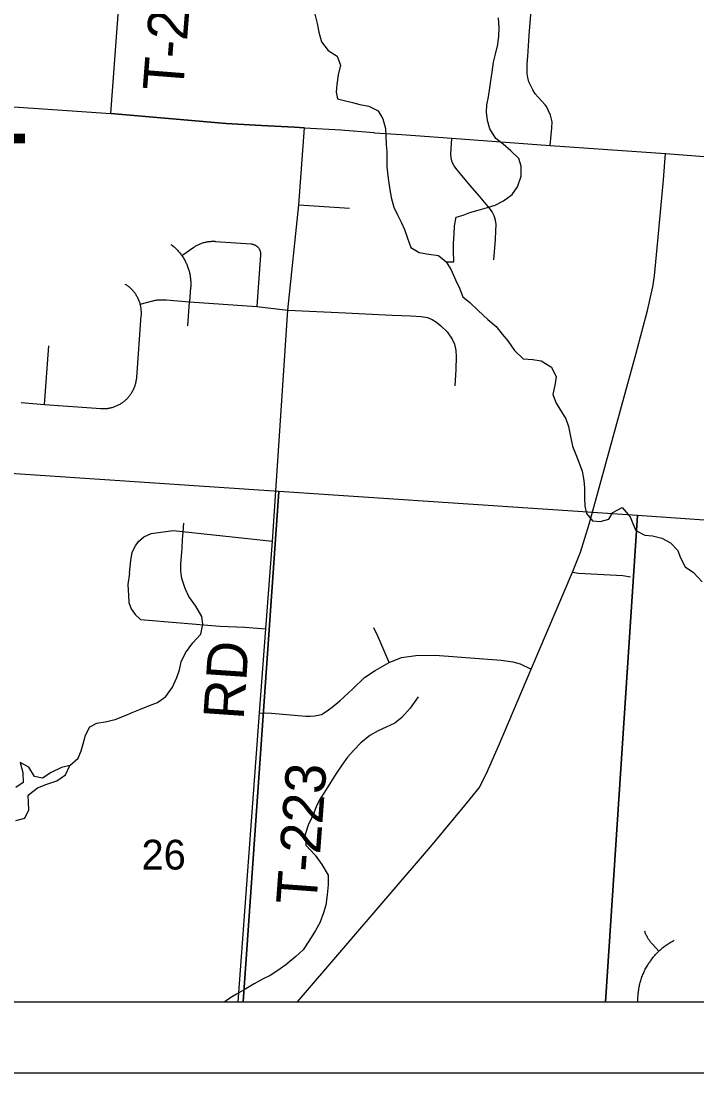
# Model space of a CAD drawing. Extents: x 0 to 34, y 0 to 22.
# Drawn here: x 3.147 to 4.098, y 14 to 15.479 of the extents above; entities that cross this region are included whole.
import ezdxf

# ---------------------------------------------------------------- set-up
doc = ezdxf.new("R2010")
doc.units = 0
for name, color, linetype in [('GM_X_Corporation', 7, 'Continuous'), ('GM_X_County_Road', 7, 'Continuous'), ('GM_X_Minor_Lake', 7, 'Continuous'), ('GM_X_Minor_River', 7, 'Continuous'), ('GM_X_Section_Text', 7, 'Continuous'), ('GM_X_State_Route', 7, 'Continuous'), ('GM_X_State_Shield', 7, 'Continuous'), ('GM_X_Township_Road', 7, 'Continuous'), ('GM_X_Township_Road_Text', 7, 'Continuous'), ('GM_X_Unincorporated_Text', 7, 'Continuous'), ('SH_Cut_Line', 7, 'Continuous'), ('SH_Data', 7, 'Continuous')]:
    doc.layers.add(name, color=color, linetype=linetype)

msp = doc.modelspace()

# ---------------------------------------------------------------- linework, layer by layer
at = {"layer": 'GM_X_Corporation'}
msp.add_lwpolyline([(2.1, 15.9442), (2.1, 14.1), (4.9875, 14.1), (5.0611, 15.2147), (5.0952, 15.7318), (4.92, 15.7429), (4.5905, 15.7634), (4.2803, 15.787), (3.9945, 15.8088), (3.3132, 15.8609), (2.8362, 15.8952), (2.7799, 15.8989), (2.6921, 15.9056), (2.5827, 15.9132), (2.2903, 15.9292)], close=True, dxfattribs=at)
at = {"layer": 'GM_X_County_Road'}
msp.add_lwpolyline([(3.5364, 14.1), (3.7263, 14.3211), (3.7718, 14.3759), (3.7918, 14.401), (3.8015, 14.4199), (3.8205, 14.4627), (3.8648, 14.5679), (3.9228, 14.7043), (3.9343, 14.7323), (3.9465, 14.7715), (4.0126, 15.012), (4.0283, 15.072), (4.0359, 15.1052), (4.0381, 15.1205), (4.0431, 15.1699), (4.051, 15.2555), (4.0539, 15.2928)], dxfattribs=at)
at = {"layer": 'GM_X_Minor_Lake'}
msp.add_lwpolyline([(3.1402, 14.3551), (3.1528, 14.3584), (3.1586, 14.3701), (3.1577, 14.3906), (3.1706, 14.4008), (3.1836, 14.4059), (3.1977, 14.4107), (3.2099, 14.4193), (3.2161, 14.4322), (3.2043, 14.4296), (3.1898, 14.4222), (3.1776, 14.4143), (3.1663, 14.4167), (3.1585, 14.4297), (3.1464, 14.4363), (3.15, 14.4226), (3.1506, 14.4082), (3.1403, 14.4015)], dxfattribs=at)
at = {"layer": 'GM_X_Minor_River'}
for points in [[(3.5608, 15.4888), (3.5641, 15.4755), (3.5662, 15.4633), (3.5702, 15.4496), (3.5796, 15.4373), (3.592, 15.4296), (3.5968, 15.4167), (3.5936, 15.4034), (3.5916, 15.3898), (3.5907, 15.3791), (3.5925, 15.3696), (3.6038, 15.3668), (3.6136, 15.3645), (3.6238, 15.3617), (3.6367, 15.3593), (3.6495, 15.3527), (3.6562, 15.3416), (3.6598, 15.3279), (3.6605, 15.3177), (3.6611, 15.3048), (3.6618, 15.2953), (3.6617, 15.2846), (3.6619, 15.274), (3.6633, 15.2611), (3.6647, 15.2508), (3.6665, 15.239), (3.6686, 15.2291), (3.6715, 15.2173), (3.6771, 15.2066), (3.6827, 15.1952), (3.6867, 15.1857), (3.6908, 15.1735), (3.6955, 15.1605), (3.7072, 15.1536), (3.7208, 15.1511), (3.7344, 15.1491), (3.7453, 15.1403), (3.7524, 15.1292), (3.7583, 15.1151), (3.7639, 15.1032), (3.7687, 15.0914), (3.7784, 15.083), (3.7904, 15.0722), (3.8039, 15.0592), (3.8156, 15.0496), (3.8242, 15.0389), (3.832, 15.0293), (3.8413, 15.0159), (3.8537, 15.004), (3.867, 15.0031), (3.8791, 15.0011), (3.8934, 14.9922), (3.9, 14.9788), (3.8988, 14.9694), (3.8952, 14.9538), (3.9, 14.9416), (3.9075, 14.9294), (3.9134, 14.9195), (3.9175, 14.9088), (3.9203, 14.8947), (3.9228, 14.8814), (3.9276, 14.8696), (3.9321, 14.8589), (3.9365, 14.846), (3.939, 14.8331), (3.94, 14.8228), (3.9399, 14.8088), (3.9405, 14.797), (3.9427, 14.7867), (3.9513, 14.7764)], [(3.7453, 15.1403), (3.7563, 15.1402), (3.7557, 15.1561), (3.7558, 15.1667), (3.7564, 15.1793), (3.7572, 15.191), (3.7593, 15.2031), (3.7691, 15.2061), (3.7787, 15.2098), (3.7904, 15.2131), (3.8034, 15.2167), (3.814, 15.22), (3.8258, 15.226), (3.838, 15.235), (3.8457, 15.2459), (3.8508, 15.261), (3.8506, 15.2751), (3.8473, 15.2857), (3.8364, 15.2965), (3.8255, 15.3057), (3.815, 15.3138), (3.8068, 15.3275), (3.8035, 15.3393), (3.8021, 15.3507), (3.8026, 15.361), (3.8047, 15.3724), (3.8067, 15.3849), (3.8083, 15.3951), (3.81, 15.4072), (3.812, 15.4209), (3.8148, 15.4326), (3.8179, 15.4459), (3.8192, 15.4576), (3.8197, 15.4694), (3.8187, 15.4834)], [(3.9513, 14.7764), (3.9619, 14.7751), (3.974, 14.7784), (3.9798, 14.7882), (3.9928, 14.7949), (4.004, 14.7819), (4.0077, 14.7724), (4.0121, 14.7625), (4.0245, 14.7563), (4.0355, 14.755), (4.0487, 14.7518), (4.0608, 14.7453), (4.0709, 14.7345), (4.0742, 14.725), (4.0816, 14.7116), (4.0933, 14.7035), (4.1053, 14.6905)], [(3.2161, 14.4322), (3.2279, 14.4427), (3.2322, 14.4529), (3.235, 14.4627), (3.2381, 14.4748), (3.2443, 14.4865), (3.2542, 14.4917), (3.266, 14.4939), (3.28, 14.4968), (3.293, 14.502), (3.3036, 14.5068), (3.3154, 14.5116), (3.328, 14.5168), (3.3394, 14.5208), (3.3512, 14.5291), (3.3604, 14.5426), (3.3666, 14.5559), (3.3702, 14.5668), (3.3729, 14.5782), (3.3788, 14.5906), (3.3891, 14.6046), (3.4003, 14.617), (3.4031, 14.631), (3.4017, 14.6416), (3.3931, 14.6562), (3.3834, 14.6699), (3.3782, 14.681), (3.3735, 14.6951), (3.3721, 14.7057), (3.3722, 14.7156), (3.373, 14.7266), (3.3739, 14.7376), (3.3744, 14.7501), (3.3753, 14.7603), (3.3766, 14.7732)], [(3.7058, 14.5288), (3.6946, 14.513), (3.6831, 14.4998), (3.6732, 14.4919), (3.661, 14.486), (3.6499, 14.4808), (3.6381, 14.4745), (3.6255, 14.464), (3.6156, 14.4538), (3.6067, 14.444), (3.5987, 14.4327), (3.5914, 14.4222), (3.5825, 14.4082), (3.574, 14.395), (3.5682, 14.3852), (3.5628, 14.3754), (3.5577, 14.3614), (3.5519, 14.3497), (3.5469, 14.3354), (3.5482, 14.3202), (3.5609, 14.306), (3.5706, 14.293), (3.5796, 14.2781), (3.5794, 14.2644), (3.5781, 14.2504), (3.5761, 14.236), (3.5726, 14.225), (3.5675, 14.211), (3.5617, 14.2001), (3.5532, 14.1865), (3.544, 14.1733), (3.534, 14.1636), (3.5199, 14.1519), (3.5073, 14.1433), (3.4977, 14.137), (3.4879, 14.1325), (3.4753, 14.1255), (3.4638, 14.1184), (3.4505, 14.1109), (3.441, 14.1053), (3.4342, 14.1)]]:
    msp.add_lwpolyline(points, dxfattribs=at)
at = {"layer": 'GM_X_State_Route'}
msp.add_line((3.6444, 15.322), (3.6823, 15.3192), dxfattribs=at)
for points in [[(2.7232, 15.3874), (2.7363, 15.3866), (2.7736, 15.3839), (2.8199, 15.3805), (2.911, 15.3744), (2.9933, 15.3683), (3.2738, 15.3489)], [(3.2738, 15.3489), (3.436, 15.3351), (3.4855, 15.332), (3.5321, 15.3297), (3.5463, 15.3288)], [(3.5463, 15.3288), (3.5971, 15.3258), (3.6434, 15.3221), (3.6444, 15.322)], [(3.6823, 15.3192), (3.7023, 15.3178), (3.7533, 15.3145), (3.8914, 15.3041), (4.0539, 15.2928)], [(4.0539, 15.2928), (4.1445, 15.2855), (4.1735, 15.283)]]:
    msp.add_lwpolyline(points, dxfattribs=at)
at = {"layer": 'GM_X_Township_Road'}
for p, q in [((3.5382, 15.2207), (3.6095, 15.2157)), ((3.382, 15.0503), (3.3845, 15.0843)), ((3.1806, 14.94), (3.1866, 15.0222))]:
    msp.add_line(p, q, dxfattribs=at)
for points in [[(3.2738, 15.3489), (3.2886, 15.5518), (3.2988, 15.6689), (3.3006, 15.7403), (3.3081, 15.7684), (3.3134, 15.8604)], [(3.8845, 15.3609), (3.8794, 15.3667), (3.8747, 15.372), (3.8707, 15.3768), (3.8672, 15.3821), (3.8642, 15.3877), (3.8618, 15.3936), (3.86, 15.3996), (3.8591, 15.4052), (3.859, 15.4105), (3.8593, 15.4186), (3.86, 15.4291), (3.8622, 15.4589), (3.866, 15.5055), (3.871, 15.57)], [(3.8914, 15.3041), (3.894, 15.329), (3.8942, 15.337), (3.8921, 15.3468), (3.8864, 15.3587), (3.8845, 15.3609)], [(3.5463, 15.3288), (3.5321, 15.3297), (3.4855, 15.332), (3.436, 15.3351), (3.2738, 15.3489)], [(3.4528, 14.1), (3.4828, 14.5062), (3.4919, 14.6245), (3.5011, 14.7476), (3.5227, 15.0726), (3.5382, 15.2207), (3.5463, 15.3288)], [(3.8125, 15.1432), (3.8145, 15.172), (3.8153, 15.184), (3.8155, 15.1929), (3.8147, 15.1991), (3.8128, 15.2052), (3.8114, 15.2081), (3.8099, 15.2109), (3.8062, 15.216), (3.7922, 15.2326), (3.782, 15.2443), (3.7601, 15.2704), (3.7565, 15.2753), (3.7538, 15.2807), (3.7524, 15.2865), (3.752, 15.2926), (3.7522, 15.2987), (3.7533, 15.3145)], [(3.3582, 15.165), (3.3593, 15.1641), (3.3604, 15.1633), (3.3615, 15.1624), (3.3626, 15.1615), (3.3636, 15.1606), (3.3646, 15.1596), (3.3656, 15.1586), (3.3666, 15.1577), (3.3676, 15.1566), (3.3685, 15.1556), (3.3694, 15.1546), (3.3703, 15.1535), (3.3712, 15.1524), (3.3721, 15.1513), (3.3729, 15.1502), (3.3737, 15.1491), (3.3745, 15.1479), (3.3753, 15.1467), (3.376, 15.1455), (3.3768, 15.1443), (3.3775, 15.143), (3.3782, 15.1418), (3.3788, 15.1405), (3.3794, 15.1392), (3.38, 15.1379), (3.3806, 15.1366), (3.3812, 15.1353), (3.3817, 15.1339), (3.3822, 15.1326), (3.3826, 15.1312), (3.3831, 15.1299), (3.3835, 15.1285), (3.3839, 15.1271), (3.3842, 15.1257), (3.3845, 15.1243), (3.3848, 15.1229), (3.3851, 15.1215), (3.3853, 15.1201), (3.3855, 15.1187), (3.3857, 15.1173), (3.3859, 15.1158), (3.386, 15.1144), (3.3861, 15.113), (3.3861, 15.1116), (3.3862, 15.1101), (3.3862, 15.1087), (3.3861, 15.1073), (3.3861, 15.1058), (3.386, 15.1044), (3.3845, 15.0843)], [(3.3737, 15.1491), (3.3905, 15.1608), (3.3915, 15.1615), (3.3924, 15.1621), (3.3934, 15.1627), (3.3944, 15.1633), (3.3954, 15.1638), (3.3965, 15.1644), (3.3975, 15.1649), (3.3986, 15.1654), (3.3996, 15.1658), (3.4007, 15.1662), (3.4018, 15.1666), (3.4029, 15.167), (3.404, 15.1674), (3.4051, 15.1677), (3.4062, 15.168), (3.4073, 15.1682), (3.4085, 15.1685), (3.4096, 15.1687), (3.4107, 15.1689), (3.4119, 15.169), (3.413, 15.1691), (3.4142, 15.1692), (3.4153, 15.1693), (3.4165, 15.1694), (3.4176, 15.1694), (3.4188, 15.1694), (3.42, 15.1693), (3.4211, 15.1692), (3.4711, 15.1656), (3.4718, 15.1655), (3.4724, 15.1654), (3.473, 15.1653), (3.4736, 15.1651), (3.4743, 15.165), (3.4749, 15.1648), (3.4755, 15.1645), (3.476, 15.1643), (3.4766, 15.164), (3.4772, 15.1637), (3.4777, 15.1634), (3.4782, 15.163), (3.4788, 15.1626), (3.4793, 15.1622), (3.4797, 15.1618), (3.4802, 15.1614), (3.4806, 15.1609), (3.481, 15.1604), (3.4814, 15.1599), (3.4818, 15.1594), (3.4822, 15.1589), (3.4825, 15.1583), (3.4828, 15.1578), (3.4831, 15.1572), (3.4833, 15.1566), (3.4835, 15.156), (3.4837, 15.1554), (3.4839, 15.1548), (3.484, 15.1541), (3.4841, 15.1535), (3.4842, 15.1529), (3.4843, 15.1523), (3.4843, 15.1516), (3.4843, 15.151), (3.4843, 15.1503), (3.4789, 15.0774)], [(3.1475, 14.9424), (3.1806, 14.94), (3.2595, 14.9342), (3.2607, 14.9341), (3.2618, 14.9341), (3.263, 14.934), (3.2642, 14.9341), (3.2654, 14.9341), (3.2666, 14.9342), (3.2677, 14.9343), (3.2689, 14.9344), (3.2701, 14.9346), (3.2712, 14.9348), (3.2724, 14.935), (3.2736, 14.9352), (3.2747, 14.9355), (3.2758, 14.9358), (3.277, 14.9362), (3.2781, 14.9365), (3.2792, 14.9369), (3.2803, 14.9373), (3.2814, 14.9378), (3.2825, 14.9383), (3.2836, 14.9388), (3.2846, 14.9393), (3.2857, 14.9398), (3.2867, 14.9404), (3.2877, 14.941), (3.2887, 14.9417), (3.2897, 14.9423), (3.2907, 14.943), (3.2916, 14.9437), (3.2925, 14.9444), (3.2934, 14.9452), (3.2943, 14.9459), (3.2952, 14.9467), (3.2961, 14.9475), (3.2969, 14.9484), (3.2977, 14.9492), (3.2985, 14.9501), (3.2993, 14.951), (3.3, 14.9519), (3.3007, 14.9529), (3.3014, 14.9538), (3.3021, 14.9548), (3.3028, 14.9558), (3.3034, 14.9568), (3.304, 14.9578), (3.3046, 14.9588), (3.3051, 14.9598), (3.3057, 14.9609), (3.3061, 14.962), (3.3066, 14.9631), (3.3071, 14.9642), (3.3075, 14.9653), (3.3079, 14.9664), (3.3082, 14.9675), (3.3086, 14.9686), (3.3089, 14.9698), (3.3091, 14.9709), (3.3094, 14.9721), (3.3096, 14.9732), (3.3098, 14.9744), (3.31, 14.9756), (3.3101, 14.9767), (3.3102, 14.9779), (3.3166, 15.0649), (3.3167, 15.066), (3.3167, 15.0672), (3.3167, 15.0683), (3.3167, 15.0695), (3.3167, 15.0706), (3.3166, 15.0717), (3.3165, 15.0729), (3.3164, 15.074), (3.3162, 15.0751), (3.3161, 15.0763), (3.3159, 15.0774), (3.3156, 15.0785), (3.3154, 15.0796), (3.3151, 15.0807), (3.3148, 15.0819), (3.3144, 15.083), (3.314, 15.0842), (3.3136, 15.0853), (3.3132, 15.0864), (3.3127, 15.0875), (3.3122, 15.0886), (3.3117, 15.0896), (3.3111, 15.0907), (3.3105, 15.0918), (3.3099, 15.0928), (3.3093, 15.0938), (3.3087, 15.0948), (3.308, 15.0958), (3.3073, 15.0968), (3.3065, 15.0977), (3.3058, 15.0986), (3.305, 15.0995), (3.3042, 15.1004), (3.3034, 15.1013), (3.3026, 15.1021), (3.3017, 15.103), (3.3008, 15.1038), (3.2999, 15.1046), (3.299, 15.1053), (3.298, 15.1061), (3.2971, 15.1068), (3.2961, 15.1075), (3.2951, 15.1081), (3.2941, 15.1087)], [(3.3151, 15.0807), (3.3326, 15.0855), (3.3337, 15.0858), (3.3349, 15.086), (3.336, 15.0863), (3.3371, 15.0865), (3.3382, 15.0866), (3.3394, 15.0868), (3.3405, 15.0869), (3.3416, 15.087), (3.3428, 15.0871), (3.3439, 15.0871), (3.3451, 15.0871), (3.3462, 15.0871), (3.3473, 15.0871), (3.3485, 15.087), (3.3514, 15.0868), (3.3845, 15.0843), (3.4789, 15.0774), (3.5227, 15.0726)], [(3.5227, 15.0726), (3.6037, 15.0687), (3.6694, 15.0655), (3.6955, 15.0643), (3.71, 15.0635), (3.7193, 15.062), (3.7258, 15.0594), (3.7315, 15.0554), (3.7379, 15.0503), (3.7469, 15.0419), (3.7536, 15.0319), (3.7569, 15.0247), (3.7591, 15.0158), (3.7592, 15.0071), (3.7587, 14.9892), (3.7575, 14.966)], [(3.3002, 14.7028), (3.3017, 14.7207), (3.3037, 14.732), (3.3086, 14.7411), (3.3128, 14.7472), (3.3201, 14.7536), (3.3304, 14.7585), (3.3616, 14.7625), (3.5011, 14.7476)], [(3.3002, 14.7028), (3.2978, 14.6869), (3.2985, 14.6714), (3.2992, 14.6615), (3.3023, 14.6524), (3.3079, 14.6444), (3.3155, 14.6375), (3.4271, 14.628), (3.4621, 14.6267), (3.4919, 14.6245)], [(3.9228, 14.7043), (3.9314, 14.7025), (3.9938, 14.6992), (4.0045, 14.6974)], [(3.6651, 14.5772), (3.6499, 14.6134), (3.6437, 14.6259)], [(3.4828, 14.5062), (3.4999, 14.5057), (3.5478, 14.5014), (3.5541, 14.5014), (3.5606, 14.5019), (3.57, 14.5042), (3.5764, 14.5081), (3.585, 14.5143), (3.5957, 14.5233), (3.614, 14.5399), (3.6306, 14.5558), (3.6454, 14.5658), (3.6651, 14.5772), (3.6824, 14.5841), (3.7028, 14.5868), (3.73, 14.5872), (3.8226, 14.5806), (3.8391, 14.5779), (3.8495, 14.5754), (3.8648, 14.5679)], [(4.0446, 14.1713), (4.0353, 14.1812), (4.0345, 14.1821), (4.0337, 14.183), (4.0329, 14.1839), (4.0322, 14.1848), (4.0315, 14.1857), (4.0308, 14.1867), (4.0302, 14.1876), (4.0296, 14.1886), (4.0289, 14.1896), (4.0284, 14.1906), (4.0278, 14.1917), (4.0273, 14.1927), (4.0268, 14.1937), (4.0263, 14.1948), (4.0258, 14.1959), (4.0254, 14.197), (4.025, 14.1981), (4.0246, 14.1992)], [(4.015, 14.1), (4.015, 14.1002), (4.0149, 14.1019), (4.0149, 14.1036), (4.015, 14.1053), (4.015, 14.107), (4.0151, 14.1087), (4.0153, 14.1104), (4.0154, 14.112), (4.0156, 14.1137), (4.0158, 14.1154), (4.0161, 14.1171), (4.0163, 14.1187), (4.0166, 14.1204), (4.017, 14.122), (4.0173, 14.1237), (4.0177, 14.1253), (4.0181, 14.127), (4.0186, 14.1286), (4.0191, 14.1302), (4.0196, 14.1318), (4.0201, 14.1334), (4.0207, 14.135), (4.0213, 14.1366), (4.0219, 14.1382), (4.0226, 14.1397), (4.0232, 14.1413), (4.0239, 14.1428), (4.0247, 14.1443), (4.0254, 14.1458), (4.0262, 14.1473), (4.027, 14.1488), (4.0279, 14.1503), (4.0287, 14.1517), (4.0296, 14.1531), (4.0305, 14.1546), (4.0315, 14.156), (4.0324, 14.1574), (4.0334, 14.1587), (4.0345, 14.1601), (4.0355, 14.1614), (4.0366, 14.1627), (4.0376, 14.164), (4.0387, 14.1653), (4.0399, 14.1665), (4.041, 14.1678), (4.0422, 14.169), (4.0434, 14.1702), (4.0446, 14.1713), (4.0458, 14.1725), (4.047, 14.1736), (4.0483, 14.1746), (4.0496, 14.1757), (4.0508, 14.1767), (4.0521, 14.1777), (4.0535, 14.1787), (4.0548, 14.1797), (4.0562, 14.1806), (4.0575, 14.1816), (4.0589, 14.1824), (4.0603, 14.1833), (4.0617, 14.1842), (4.0631, 14.185), (4.0646, 14.1858), (4.066, 14.1866)]]:
    msp.add_lwpolyline(points, dxfattribs=at)
at = {"layer": 'GM_X_Unincorporated_Text'}
for points in [[(2.9453, 14.1), (3.4598, 14.1), (3.51, 14.8176), (2.9993, 14.8517)], [(3.4598, 14.1), (3.9696, 14.1), (4.0145, 14.7837), (3.51, 14.8176)], [(3.9696, 14.1), (4.4753, 14.1), (4.5173, 14.7485), (4.0145, 14.7837)]]:
    msp.add_lwpolyline(points, close=True, dxfattribs=at)
at = {"layer": 'SH_Cut_Line'}
msp.add_lwpolyline([(2.1, 15.9442), (2.1, 14.1), (8.9, 14.1), (8.9, 15.4827), (8.6741, 15.4976), (7.6503, 15.5653), (6.838, 15.6206), (6.624, 15.6351), (6.4, 15.6498), (6.1109, 15.6683), (5.9419, 15.6782), (5.0952, 15.7318), (4.92, 15.7429), (4.5905, 15.7634), (4.2803, 15.787), (3.9945, 15.8088), (3.3132, 15.8609), (2.8362, 15.8952), (2.7799, 15.8989), (2.6921, 15.9056), (2.5827, 15.9132), (2.2903, 15.9292)], close=True, dxfattribs=at)
at = {"layer": 'SH_Data'}
msp.add_line((2, 14), (9, 14), dxfattribs=at)

# ---------------------------------------------------------------- texts
at = {"layer": 'GM_X_Section_Text'}
msp.add_text('26', height=0.04186, rotation=0, dxfattribs=at).set_placement((3.3169, 14.286))
at = {"layer": 'GM_X_State_Shield'}
msp.add_text('204', height=0.13184, dxfattribs=at).set_placement((2.8642, 15.2773))
at = {"layer": 'GM_X_Township_Road_Text'}
for s, rotation, p in [('T-223', 85.4937, (3.3752, 15.379)), ('RD', 86.0533, (3.4604, 14.4958)), ('T-223', 85.7741, (3.5627, 14.2353))]:
    msp.add_text(s, height=0.05682, rotation=rotation, dxfattribs=at).set_placement(p)

doc.saveas('drawing.dxf')
